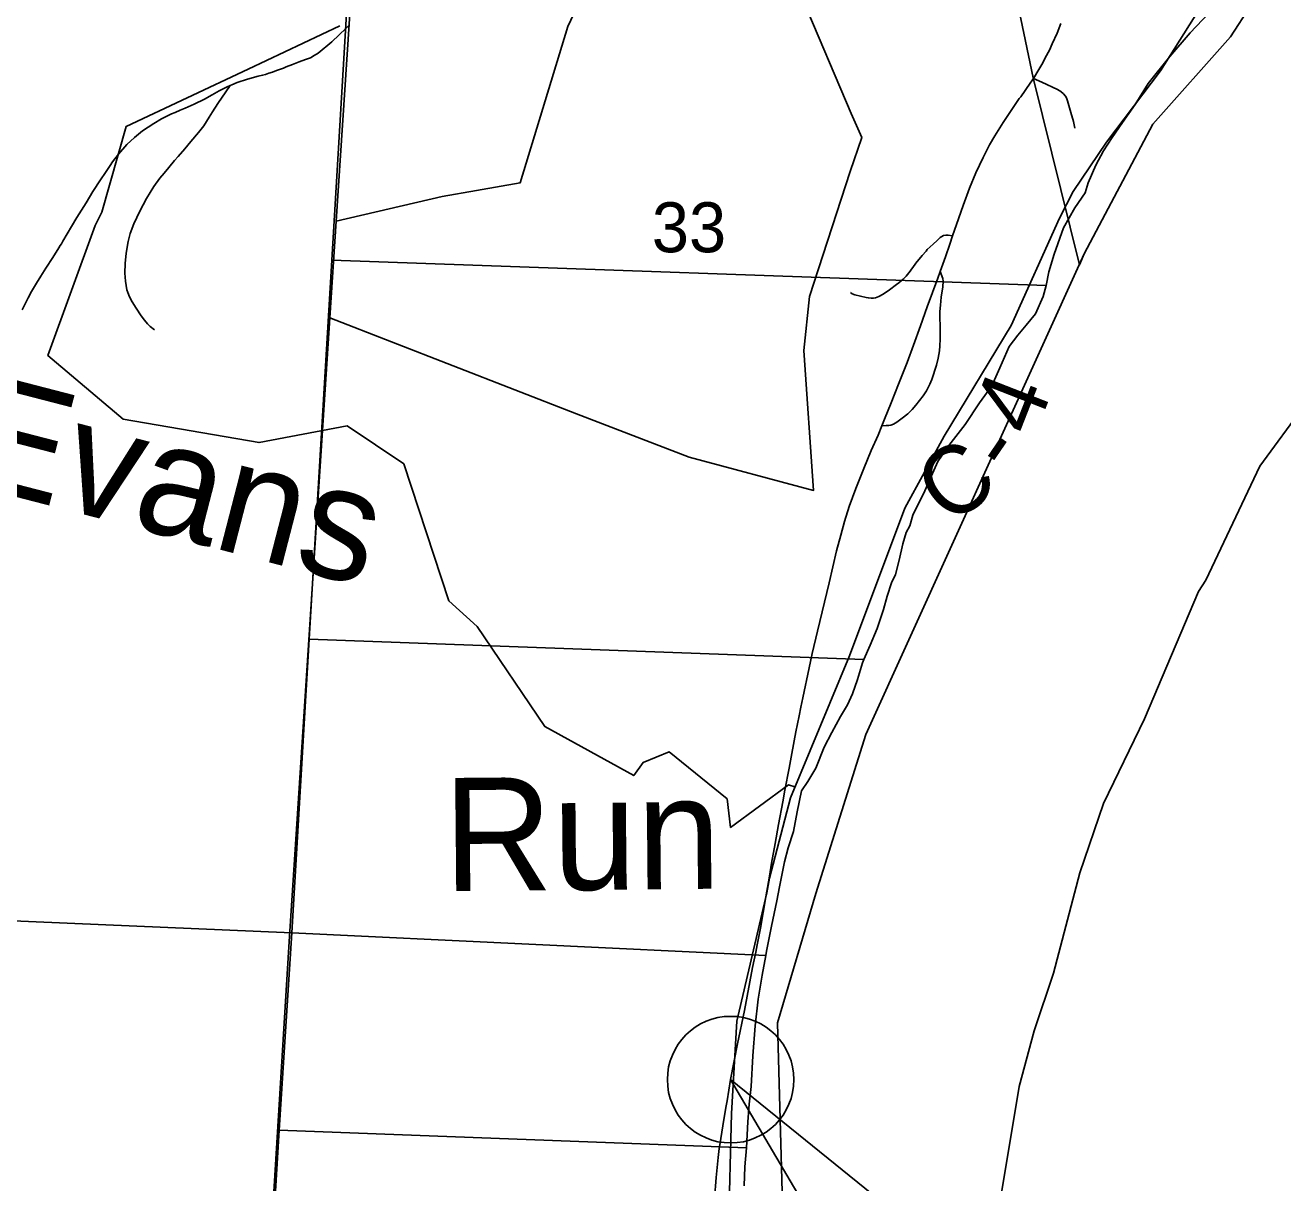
# Model space of a CAD drawing. Extents: x 0 to 34, y 0 to 22.
# Drawn here: x 5.906 to 6.959, y 17.749 to 18.718 of the extents above; entities that cross this region are included whole.
import ezdxf

# ---------------------------------------------------------------- set-up
doc = ezdxf.new("R2010")
doc.units = 0
for name, color, linetype in [('Default', 7, 'Continuous'), ('GM_X_City_Street', 7, 'Continuous'), ('GM_X_County_Road', 7, 'Continuous'), ('GM_X_County_Road_Text', 7, 'Continuous'), ('GM_X_Major_River', 7, 'Continuous'), ('GM_X_Minor_River', 7, 'Continuous'), ('GM_X_Minor_River_Text', 7, 'Continuous'), ('GM_X_Section', 7, 'Continuous'), ('GM_X_Section_Text', 7, 'Continuous'), ('GM_X_State_Route', 7, 'Continuous'), ('GM_X_Township_Road', 7, 'Continuous'), ('SH_Text', 7, 'Continuous')]:
    doc.layers.add(name, color=color, linetype=linetype)

msp = doc.modelspace()

# ---------------------------------------------------------------- linework, layer by layer
at = {"layer": 'Default'}
for points in [[(6.0603, 16.8624), (6.127, 17.9511), (6.1612, 18.4732), (6.1665, 18.5542), (6.1773, 18.7192), (6.1898, 18.9313), (6.195, 19.011), (6.2406, 19.7849), (6.241, 19.7927), (6.2413, 19.8018), (6.2418, 19.8127), (6.2424, 19.8289), (6.2426, 19.8432), (6.2426, 19.8474), (6.2427, 19.8586), (6.2428, 19.8591), (6.2428, 19.8627), (6.2428, 19.867), (6.2428, 19.8705), (6.2431, 19.8748), (6.2438, 19.8792), (6.3032, 20.9), (2.1, 20.9), (2.1, 16.1239)], [(8.9, 20.9), (6.3032, 20.9), (6.2438, 19.8792), (6.2431, 19.8748), (6.2428, 19.8705), (6.2428, 19.867), (6.2428, 19.8627), (6.2428, 19.8591), (6.2427, 19.8586), (6.2426, 19.8474), (6.2426, 19.8432), (6.2424, 19.8289), (6.2418, 19.8127), (6.2413, 19.8018), (6.241, 19.7927), (6.2406, 19.7849), (6.195, 19.011), (6.1898, 18.9313), (6.1773, 18.7192), (6.1665, 18.5542), (6.1612, 18.4732), (6.127, 17.9511), (6.0603, 16.8624)], [(6.7072, 18.8801), (6.7501, 18.6742), (6.7888, 18.5176), (6.7929, 18.5267), (6.8504, 18.6353), (6.9154, 18.7085), (6.9494, 18.7612)], [(6.5502, 17.3673), (6.5359, 17.8831), (6.568, 17.9912), (6.61, 18.1245), (6.7929, 18.5267), (6.8504, 18.6353), (6.9154, 18.7085), (6.9494, 18.7612), (7.0197, 18.8208)], [(6.3676, 18.7324), (6.3605, 18.7171), (6.3204, 18.5862), (6.2841, 18.5798), (6.2552, 18.5747), (6.1665, 18.5542), (6.1612, 18.4732), (6.3677, 18.3929), (6.4621, 18.3567), (6.5662, 18.3288), (6.558, 18.4459), (6.5628, 18.4911), (6.5968, 18.5958), (6.6066, 18.6243), (6.5977, 18.6442), (6.5566, 18.7411)]]:
    msp.add_lwpolyline(points, dxfattribs=at)
at = {"layer": 'GM_X_City_Street'}
msp.add_lwpolyline([(6.7851, 18.6321), (6.7838, 18.6375), (6.7816, 18.6451), (6.7789, 18.6548), (6.778, 18.6573), (6.7771, 18.6589), (6.7755, 18.6608), (6.7732, 18.6628), (6.7706, 18.6644), (6.7573, 18.6705), (6.7503, 18.6736)], dxfattribs=at)
at = {"layer": 'GM_X_County_Road'}
for points in [[(5.9034, 18.4799), (5.9084, 18.4899), (5.9113, 18.4953), (5.9155, 18.5023), (5.9191, 18.5081), (5.9234, 18.5149), (5.9291, 18.5238), (5.9341, 18.5317), (5.9353, 18.5337), (5.9363, 18.5353), (5.9376, 18.5373), (5.9447, 18.5497), (5.9492, 18.5571), (5.9571, 18.5696), (5.9627, 18.579), (5.9692, 18.5888), (5.9733, 18.595), (5.9771, 18.6007), (5.9792, 18.6038), (5.9841, 18.6103), (5.9911, 18.6182), (5.9975, 18.6243), (6.0044, 18.6297), (6.0137, 18.636), (6.0202, 18.6398), (6.0286, 18.6439), (6.0315, 18.6451), (6.0359, 18.647), (6.04, 18.6487), (6.0476, 18.6521), (6.0563, 18.6563), (6.0627, 18.66), (6.0686, 18.6633), (6.0747, 18.6664), (6.0778, 18.6678), (6.0791, 18.6684), (6.0835, 18.6702), (6.0922, 18.6731), (6.1011, 18.6754), (6.1048, 18.6763), (6.1072, 18.677), (6.1101, 18.678), (6.113, 18.679), (6.1165, 18.6802), (6.1223, 18.6823), (6.1246, 18.6833), (6.1298, 18.6853), (6.1355, 18.6875), (6.1408, 18.6894), (6.145, 18.6909), (6.148, 18.6927), (6.1513, 18.6947), (6.1627, 18.7044), (6.1748, 18.7157), (6.1775, 18.7186)], [(6.6235, 18.3828), (6.627, 18.383), (6.6294, 18.3832), (6.6309, 18.3834), (6.6332, 18.3843), (6.6359, 18.3859), (6.6404, 18.3891), (6.6452, 18.393), (6.6487, 18.3965), (6.652, 18.4002), (6.6581, 18.408), (6.6608, 18.4121), (6.6637, 18.4177), (6.6654, 18.4217), (6.6692, 18.4335), (6.6707, 18.4395), (6.6717, 18.4456), (6.6721, 18.4499), (6.6722, 18.4555), (6.6722, 18.4616), (6.6721, 18.4783), (6.6723, 18.4814), (6.6724, 18.4838), (6.6731, 18.4906), (6.6744, 18.4993), (6.6749, 18.5038), (6.6744, 18.5061), (6.6723, 18.512)]]:
    msp.add_lwpolyline(points, dxfattribs=at)
at = {"layer": 'GM_X_Major_River'}
for points in [[(7.0418, 18.8968), (7.0196, 18.8796), (6.9736, 18.835), (6.9379, 18.795), (6.8924, 18.7367), (6.8567, 18.68), (6.8115, 18.6202), (6.7837, 18.5791), (6.7721, 18.5567), (6.7316, 18.4669), (6.6757, 18.3741), (6.6427, 18.314), (6.5963, 18.1904), (6.5469, 18.0714), (6.5294, 18.0041), (6.5271, 17.9919), (6.5019, 17.8844), (6.4976, 17.8073), (6.4924, 17.6107)], [(6.7199, 17.719), (6.7384, 17.8299), (6.751, 17.8763), (6.7671, 17.9246), (6.7891, 18.0086), (6.8089, 18.0667), (6.8434, 18.1375), (6.8887, 18.244), (6.8947, 18.2535), (6.94, 18.349), (7.0152, 18.4518)]]:
    msp.add_lwpolyline(points, dxfattribs=at)
at = {"layer": 'GM_X_Minor_River'}
msp.add_lwpolyline([(6.5505, 18.0806), (6.5452, 18.0824), (6.4967, 18.0467), (6.4938, 18.0705), (6.4454, 18.11), (6.4235, 18.101), (6.4157, 18.09), (6.3411, 18.1311), (6.2846, 18.2148), (6.2608, 18.2362), (6.2232, 18.3509), (6.1757, 18.3827), (6.1019, 18.3688), (5.9881, 18.3883), (5.9251, 18.4416), (5.9647, 18.5505), (5.9702, 18.5616), (5.9906, 18.6335), (6.0928, 18.6815), (6.1694, 18.7178)], dxfattribs=at)
at = {"layer": 'GM_X_Section'}
for points in [[(5.1485, 19.0298), (6.1895, 18.9865), (6.1775, 18.7705), (6.1627, 18.5214), (6.1439, 18.2043), (6.1294, 17.9583), (5.0782, 18.0036), (5.1344, 18.7947)], [(6.9101, 18.7428), (6.9023, 18.7336), (6.8815, 18.7119), (6.8645, 18.6921), (6.8464, 18.6693), (6.8355, 18.6519), (6.8249, 18.6367), (6.8163, 18.6241), (6.8091, 18.6131), (6.8027, 18.601), (6.7963, 18.5862), (6.7937, 18.5778), (6.785, 18.5653), (6.7756, 18.5486), (6.7677, 18.5266), (6.7632, 18.5118), (6.761, 18.5002), (6.1627, 18.5214), (6.1775, 18.7705)], [(6.1627, 18.5214), (6.761, 18.5002), (6.7584, 18.491), (6.752, 18.4765), (6.7444, 18.467), (6.7373, 18.4587), (6.7301, 18.4492), (6.7222, 18.4313), (6.7154, 18.4162), (6.7053, 18.4021), (6.6932, 18.3839), (6.6796, 18.3664), (6.6702, 18.3531), (6.6593, 18.3284), (6.6495, 18.308), (6.6469, 18.2992), (6.6439, 18.2935), (6.6409, 18.2841), (6.6379, 18.2704), (6.6349, 18.2583), (6.6315, 18.2514), (6.6278, 18.2401), (6.6248, 18.2291), (6.6195, 18.2131), (6.6135, 18.1991), (6.6084, 18.1872), (6.1439, 18.2043)], [(6.6084, 18.1872), (6.6071, 18.1843), (6.603, 18.1706), (6.5989, 18.1585), (6.5947, 18.1494), (6.5887, 18.1395), (6.5816, 18.1262), (6.5752, 18.1137), (6.568, 18.0963), (6.5613, 18.0852), (6.556, 18.0773), (6.5526, 18.0598), (6.5493, 18.0431), (6.5451, 18.0295), (6.5418, 18.0177), (6.5377, 17.9969), (6.5355, 17.9851), (6.531, 17.9639), (6.5269, 17.943), (6.5262, 17.9393), (6.1294, 17.9583), (6.1439, 18.2043)], [(5.0782, 18.0036), (6.1294, 17.9583), (6.1188, 17.7931), (6.0808, 17.1618), (6.0674, 16.9363), (5.0081, 16.9831)], [(6.5262, 17.9393), (6.5232, 17.9229), (6.5198, 17.9029), (6.5173, 17.8805), (6.5154, 17.8555), (6.514, 17.8297), (6.5122, 17.8149), (6.5111, 17.8001), (6.5101, 17.7785), (6.1188, 17.7931), (6.1294, 17.9583)]]:
    msp.add_lwpolyline(points, close=True, dxfattribs=at)
msp.add_lwpolyline([(6.0808, 17.1618), (6.1188, 17.7931), (6.5101, 17.7785), (6.5086, 17.7626), (6.5082, 17.7467)], dxfattribs=at)
at = {"layer": 'GM_X_State_Route'}
for points in [[(6.7503, 18.6736), (6.7548, 18.6812), (6.7581, 18.6868), (6.7603, 18.6909), (6.7637, 18.6974), (6.7661, 18.7025), (6.7701, 18.7115), (6.7732, 18.7196)], [(6.7397, 18.6583), (6.7476, 18.6697), (6.7503, 18.6736)], [(6.4833, 17.7357), (6.4847, 17.7537), (6.4863, 17.7704), (6.4872, 17.7778), (6.4876, 17.7809), (6.4902, 17.7969), (6.4929, 17.8122), (6.4938, 17.8177), (6.4968, 17.8355), (6.5025, 17.8654), (6.5084, 17.8934), (6.5152, 17.9294), (6.5179, 17.9422), (6.5191, 17.9483), (6.5218, 17.9623), (6.5263, 17.9886), (6.5292, 18.0057), (6.5311, 18.0167), (6.5341, 18.0332), (6.5369, 18.0491), (6.5405, 18.0681), (6.5423, 18.0778), (6.5457, 18.0962), (6.548, 18.1084), (6.5515, 18.1267), (6.5541, 18.1401), (6.5557, 18.1473), (6.5573, 18.1552), (6.5626, 18.1801), (6.5652, 18.1922), (6.5696, 18.211), (6.5793, 18.2515), (6.5855, 18.2781), (6.589, 18.2913), (6.5921, 18.3027), (6.5961, 18.3152), (6.6016, 18.3304), (6.6083, 18.3472), (6.6146, 18.3621), (6.6204, 18.3751), (6.6235, 18.3828), (6.6257, 18.3884), (6.6312, 18.4022), (6.6374, 18.4178), (6.6445, 18.4357), (6.6498, 18.4503), (6.6557, 18.4666), (6.6614, 18.4824), (6.6702, 18.5063), (6.6723, 18.512), (6.6767, 18.5244), (6.6803, 18.535), (6.6826, 18.5419), (6.6858, 18.5515), (6.6915, 18.5673), (6.6969, 18.5819), (6.7022, 18.5945), (6.7083, 18.6075), (6.7137, 18.618), (6.718, 18.6257), (6.7249, 18.6367), (6.7385, 18.6567), (6.7397, 18.6583)]]:
    msp.add_lwpolyline(points, dxfattribs=at)
at = {"layer": 'GM_X_Township_Road'}
for points in [[(5.9912, 18.4967), (5.9905, 18.5002), (5.99, 18.5039), (5.9896, 18.5107), (5.9898, 18.5188), (5.9906, 18.5274), (5.9922, 18.5372), (5.994, 18.5438), (5.9971, 18.5519), (6.002, 18.5626), (6.0076, 18.573), (6.0138, 18.5831), (6.0189, 18.5901), (6.0223, 18.5943), (6.0264, 18.5992), (6.0312, 18.6049), (6.034, 18.6082), (6.0396, 18.6148), (6.0447, 18.6208), (6.0513, 18.6285), (6.0555, 18.6339), (6.06, 18.6412), (6.0628, 18.6456), (6.0674, 18.6527), (6.0741, 18.6624), (6.0778, 18.6678)], [(6.5971, 18.4943), (6.5986, 18.4934), (6.6008, 18.4926), (6.6103, 18.4903), (6.6121, 18.4899), (6.6146, 18.4896), (6.6164, 18.4897), (6.6182, 18.4901), (6.621, 18.4912), (6.6244, 18.4931), (6.6299, 18.4967), (6.6357, 18.501), (6.6377, 18.5025), (6.6396, 18.5041), (6.6413, 18.5056), (6.6422, 18.5064), (6.6437, 18.5081), (6.646, 18.5109), (6.647, 18.5122), (6.6483, 18.514), (6.6493, 18.5153), (6.652, 18.519), (6.6571, 18.5253), (6.6604, 18.5289), (6.6615, 18.5303), (6.6663, 18.5349), (6.6697, 18.5381), (6.6722, 18.5404), (6.6737, 18.5414), (6.675, 18.5421), (6.677, 18.5425), (6.6789, 18.5425), (6.6826, 18.5419)], [(6.0144, 18.4631), (6.0108, 18.466), (6.0084, 18.4683), (6.0059, 18.4712), (6.0031, 18.4749), (5.9989, 18.4814), (5.9955, 18.4865), (5.9933, 18.4908), (5.9919, 18.4944), (5.9912, 18.4967)]]:
    msp.add_lwpolyline(points, dxfattribs=at)
at = {"layer": 'SH_Text'}
msp.add_lwpolyline([(6.5502, 17.3673), (6.5359, 17.8831), (6.568, 17.9912), (6.61, 18.1245), (6.7929, 18.5267), (6.8504, 18.6353), (6.9154, 18.7085), (6.9494, 18.7612), (7.0197, 18.8208)], dxfattribs=at)
msp.add_lwpolyline([(6.9128, 17.129), (6.4968, 17.8355), (7.122, 17.3299), (6.9128, 17.3299)], close=True, dxfattribs=at)
msp.add_circle((6.4968, 17.8355), 0.053, dxfattribs=at)

# ---------------------------------------------------------------- texts
at = {"layer": 'GM_X_County_Road_Text'}
for s, rotation, p in [('4', 68.6685, (6.7508, 18.3723)), ('-', 55.695, (6.7311, 18.3407)), ('C', 37.3937, (6.6804, 18.298))]:
    msp.add_text(s, height=0.0568, rotation=rotation, dxfattribs=at).set_placement(p)
at = {"layer": 'GM_X_Minor_River_Text'}
for s, rotation, p in [('Evans', 345.5114, (5.8496, 18.3359)), ('Run', 0.5113, (6.2566, 17.9933))]:
    msp.add_text(s, height=0.0947, rotation=rotation, dxfattribs=at).set_placement(p)
at = {"layer": 'GM_X_Section_Text'}
msp.add_text('33', height=0.04186, rotation=0, dxfattribs=at).set_placement((6.4308, 18.5281))

doc.saveas('drawing.dxf')
